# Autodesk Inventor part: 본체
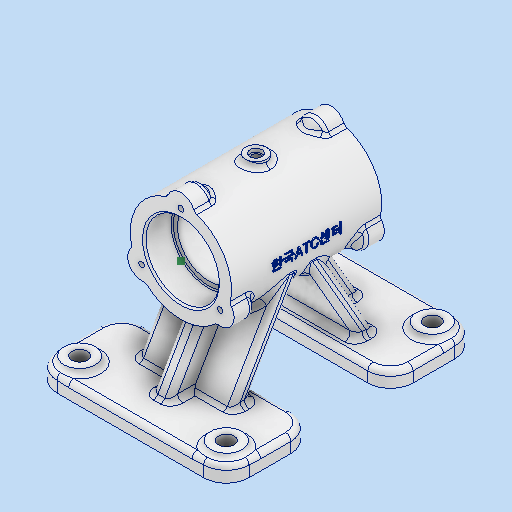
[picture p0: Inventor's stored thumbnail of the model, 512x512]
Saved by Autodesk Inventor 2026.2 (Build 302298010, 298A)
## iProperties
Created: 2026-04
Part Number: 본체
Material: 알루미늄 6061
Document SubType Name: Modeling
Designer: PC-2-06
Mass: 746.295 g
Surface Area: 674.064 cm^2
Volume: 276.405 cm^3
Density: 2.7 g/cm^3
Appearance: 알루미늄 - 평지
Author: PC-2-06
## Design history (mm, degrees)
sketch "스케치1"
  geometry: C1 r 29 at (0, 0); 1 further point
  constraints: 1 centre point, 1 coincident
  dimensions: "d0" = 58 diameter of C1
extrude "돌출1" new body sketch "스케치1" stored distance "d1" = 86; taper "d2" = 0 deg
sketch "스케치2" dims "d3" = 52
  geometry: L1 (0, 41.8)-(0, -40.8) reference; L2 (-40.6, 0)-(40.6, 0) reference; C1 r 8 at (0, 26); C2 r 8 at (-22.517, -13); C3 r 8 at (22.517, -13); 2 further points
  constraints: 3 centre point, 1 coincident, 1 point on line, 1 vertical alignment, 9 other
  dimensions: "d4" = 16 diameter of C1; "d7" = 360 deg dimension on point (0, 0) C1.centre (derived)
extrude "돌출2" join sketch "스케치2" distance "d9" = 10; taper "d10" = 0 deg
sketch "스케치15"
  geometry: 1 further point
node "작업 평면1"
sketch "스케치4"
  geometry: L1 (55, 72)-(-55, 72); L2 (-55, 72)-(-55, 22); L3 (-55, 22)-(55, 22); L4 (55, 22)-(55, 72); L5 (55, -22)-(-55, -22); L6 (-55, -22)-(-55, -72); L7 (-55, -72)-(55, -72); L8 (55, -72)-(55, -22); L9 (0, -100.8)-(0, 100.8) reference; L10 (-77, 0)-(77, 0) reference; 1 further point
  constraints: 16 end point, 4 parallel, 2 horizontal, 2 perpendicular, 1 point on line, 3 other
  dimensions: "d24" = 144 distance between parallel lines of L7 L1; "d25" = 110 distance of L1.start L1.end; "d26" = 50 distance of L3.end L1.start; "d27" = 44 distance of L5.end L2.end
extrude "돌출3" join sketch "스케치4" distance "d28" = 9; taper "d29" = 0 deg
fillet "모깎기1" dims "d30" = 13
sketch "스케치5"
  geometry: C1 r 9 at (-42, -59); C2 r 9 at (42, -59); A1 r 13 centre (-42, -59) between (-55, -59) and (-42, -72) reference; A2 r 13 centre (42, -59) between (42, -72) and (55, -59) reference; 1 further point
  constraints: 2 centre point, 2 coincident
  dimensions: "d31" = 18 diameter of C1; "d33" = 18 diameter of C2
extrude "돌출5" join sketch "스케치5" distance "d41" = 3; taper "d42" = 0 deg
sketch "스케치7"
  geometry: C1 r 9 at (0, 0) reference; C2 r 9 at (84, 0) reference; C3 r 4.5 at (0, 0); C4 r 4.5 at (84, 0); 1 further point
  constraints: 2 centre point, 2 coincident
  dimensions: "d43" = 9 diameter of C3; "d44" = 9 diameter of C4
extrude "돌출6" cut sketch "스케치7" extent not by distance; stored distance "d45" = 0; taper "d46" = 0 deg
sketch "스케치8"
  geometry: L1 (-29, -43)-(-29, 43) reference; L2 (27.942, 43)-(-7.25, 43) reference; L3 (-72, 59)-(-72, 35) reference; L4 (-72, 22)-(-72, 35) reference; L5 (-63, 35)-(-63, 22) reference; L6 (-63, 59)-(-63, 35) reference; L7 (-63, -59)-(-63, -35) reference; L8 (-63, -22)-(-63, -35) reference; L9 (-60, -50)-(-60, -68) reference; L10 (-63, -50)-(-63, -68) reference; L11 (-72, -59)-(-72, -35) reference; L12 (-72, -22)-(-63, -22) reference; L13 (-63, 32)-(-7.574, 0); L14 (-7.574, 0)-(-63, -32); L15 (-93.2, 0)-(55.2, 0) reference; L16 (-67.431, 43.796)-(0, 4.865); L17 (0, -4.865)-(-67.337, -43.742); L18 (0, 100.8)-(0, -100.8) reference; L19 (0, 4.865)-(0, -4.865); 3 further points
  constraints: 10 end point, 5 point on line, 2 parallel, 1 collinear, 1 other
  dimensions: "d48" = 10 distance of L5.end L13.start; "d49" = 60 deg angle of L14 L13; "d50" = 8 distance between parallel lines of L13 L16; "d51" = 8 distance between parallel lines of L14 L17
extrude "돌출7" join sketch "스케치8" stored distance "d52" = 54; taper "d53" = 0 deg
sketch "스케치9"
  geometry: L1 (-10.583, 10.975)-(-63, 41.238) reference; L2 (-10.583, -10.975)-(-63, -41.238) reference; L3 (-10.583, 1.737)-(-63, 32) reference; L4 (0, 18.721)-(-63, 55.094); L5 (-63, 68)-(-63, 50) reference; L6 (-63, 35)-(-63, 59) reference; L7 (0, 4.865)-(-63, 41.238); L8 (0, 100.8)-(0, -100.8) reference; 2 further points
  constraints: 4 end point, 4 point on line, 2 parallel
  dimensions: "d54" = 12 distance between parallel lines of L1 L4; "d55" = 12 distance between parallel lines of L4 L7
extrude "돌출8" join sketch "스케치9" stored distance "d56" = 10; taper "d57" = 0 deg
sketch "스케치10"
  geometry: L1 (0, 100.8)-(0, -100.8) reference; L2 (-93.2, 0)-(55.2, 0) reference; L3 (0, 43)-(21, 43); L4 (21, 43)-(21, 27.6); L5 (20.4, 27)-(0, 27); L6 (0, 27)-(0, 43); L7 (27.942, 43)-(-7.25, 43) reference; L8 (0, 27)-(18, 27); L9 (18, 27)-(18, -27); L10 (18, -27)-(0, -27); L11 (0, -27)-(0, 27); L12 (0, -43)-(21, -43); L13 (21, -43)-(21, -27.6); L14 (20.4, -27)-(0, -27); A1 r 0.6 centre (20.4, 27.6) between (20.4, 27) and (21, 27.6); A2 r 0.6 centre (20.4, -27.6) between (21, -27.6) and (20.4, -27); 6 further points
  constraints: 22 end point, 6 point on line, 4 parallel, 4 point on circle, 4 tangent, 3 symmetric about line, 2 centre point, 2 horizontal, 2 perpendicular, 1 equal radius
  dimensions: "d58" = 21 distance of point (21, 27) L5.end; "d59" = 16 distance of L3.end point (21, 27); "d60" = 18 distance of L9.end L10.end; "d61" = 54 distance of L8.end L9.end; "d62" = 0.6 radius of A1 (derived)
revolve "회전1" sketch "스케치10" stored, may be unused: angle "d63" = 90 deg
chamfer "모따기1" distance "d64" = 1; stored, may be unused: second distance "d65" = 2, angle "d66" = 45 deg
node "작업 평면2"
sketch "스케치12"
  geometry: C1 r 6 at (0, 0); 1 further point
  constraints: 1 centre point, 1 coincident
  dimensions: "d73" = 12 diameter of C1
extrude "돌출9" join sketch "스케치12" stored distance "d74" = 10; taper "d75" = 0 deg
sketch "스케치13"
  geometry: 2 further points
  constraints: 1 coincident
hole "구멍2" sketch "스케치13" at (0, 0) diameter "d76" = 4.917; stored, may be unused: countersink angle "d80" = 90 deg, drill point angle "d82" = 118 deg; dims "d77" = 15, "d78" = 7, "d79" = 2, "d81" = 17.1
fillet "모깎기5" dims "d86" = 3
fillet "모깎기6" dims "d87" = 3
fillet "모깎기7" dims "d88" = 3
fillet "모깎기8" dims "d89" = 3
node "작업 평면3"
sketch "스케치14"
  geometry: L1 (-72, -72)-(-72, -59) reference; 2 further points
  constraints: 1 other
  dimensions: "d91" = 0 distance of point (0, 0) point (0, 0); "d92" = 72 distance from line of L1 point (0, 0)
feature "엠보싱1" sketch "스케치14" dims "d0" = 58, "d93" = 0.5, "d94" = 0
sketch "스케치16"
  geometry: L1 (34, 33)-(0, -1); L2 (0, 100.814)-(0, -100.814) reference; L3 (-96.402, 0)-(74.41, 0) reference; L4 (34, -33)-(34, -43) reference; L5 (27.942, -33)-(34, -33) reference; L6 (34, 43)-(34, 33) reference; L7 (27.942, 33)-(34, 33) reference; L8 (-7.25, -43)-(27.942, -43) reference; L9 (26, -43)-(26, -25); L10 (34, -33)-(26, -25); L11 (1, 0)-(0, 1); L12 (34, -33)-(26, -33); 2 further points
  constraints: 10 end point, 6 point on line, 1 vertical
  dimensions: "d96" = 16 diameter of L4 L9; "d97" = 45 deg angle of L9 L10
revolve "회전3" sketch "스케치16" stored, may be unused: angle "d98" = 180 deg
sketch "스케치17" dims "d102" = 52
  geometry: L1 (0, -93.2)-(0, 55.2) reference; L2 (-77.014, 0)-(77.014, 0) reference; 5 further points
  constraints: 1 coincident, 1 point on line, 1 vertical alignment, 6 other
  dimensions: "d105" = 360 deg dimension on point (0, 0) point (0, 26) (derived)
hole "구멍3" sketch "스케치17" at (0, 26), (22.517, -13), (-22.517, -13) diameter "d107" = 3.242; stored, may be unused: countersink angle "d111" = 90 deg, drill point angle "d113" = 118 deg; dims "d108" = 8, "d109" = 4, "d110" = 2, "d112" = 10
fillet "모깎기9" dims "d114" = 3
fillet "모깎기10" dims "d115" = 3
feature "ϯ耀ϱ耀ϳ耀ϵ耀Ϸ耀Ϲ耀ϻ耀Ͻ耀" dims "d0" = 58, "d1" = 86, "d2" = 0, "d3" = 52, "d4" = 16, "d5" = 30, "d7" = 360 deg (derived), "d9" = 10, "d10" = 0, "d23" = -72, "d24" = 144, "d25" = 110, "d26" = 50, "d27" = 44, "d28" = 9, "d29" = 0, "d30" = 13, "d31" = 18, "d33" = 18, "d41" = 3, "d42" = 0, "d43" = 9, "d44" = 9, "d45" = 0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
node "솔리드1"
mirror "미러1"
mirror "미러2"
mirror "미러3"
mirror "미러4"
pattern_circular "원형 패턴2" dims angle "d100" = 360 deg
mirror "미러5"
mirror "미러6"
node "스케치 - 원형 패턴1" dims "d7" = 360 deg (derived)
node "스케치 - 원형 패턴3" dims "d105" = 360 deg (derived)
feature "A9D066F2-1C7D-4E18-AEED-F7BC21143FA4" dims "d76" = 4.917, "d77" = 15, "d78" = 7, "d79" = 2, "d80" = 90 deg, "d81" = 17.1, "d82" = 118 deg
